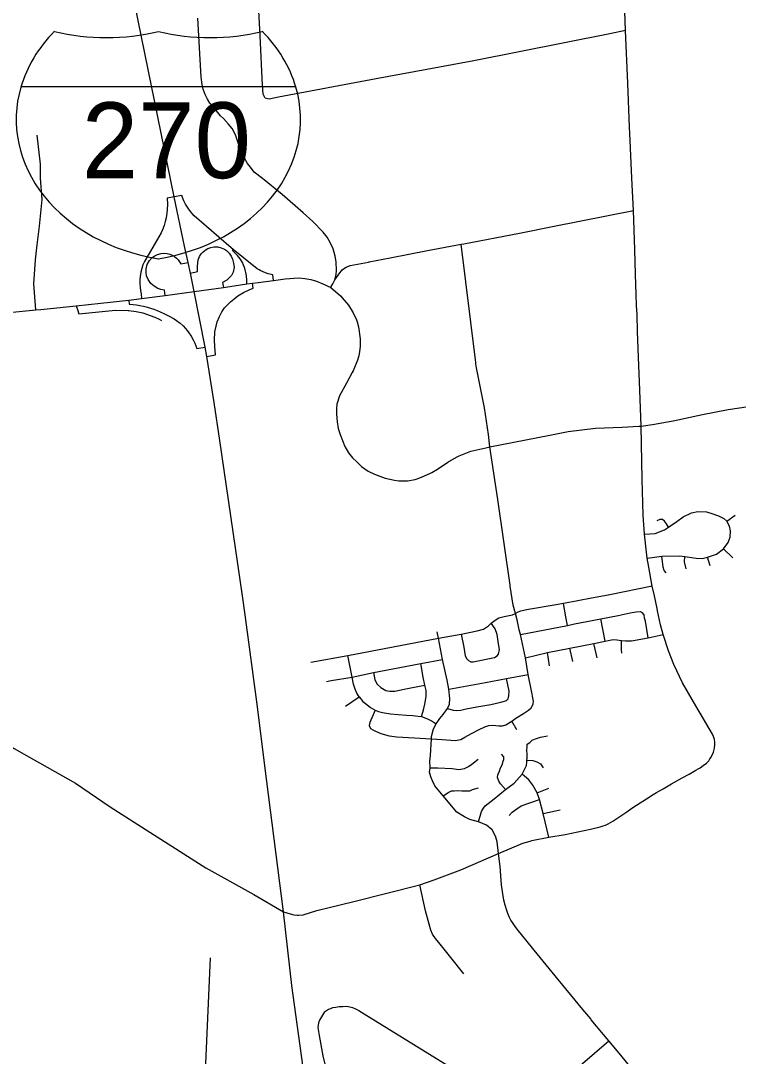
# Model space of a CAD drawing. Extents: x 1755200 to 1902939, y 644115 to 788070.
# Drawn here: x 1791519 to 1800983, y 731049 to 744708 of the extents above; entities that cross this region are included whole.
import ezdxf

# ---------------------------------------------------------------- set-up
doc = ezdxf.new("R2010")
doc.units = 0
for name, color, linetype in [('GM_X_City_Street', 7, 'Continuous'), ('GM_X_County_Road', 7, 'Continuous'), ('GM_X_Interchange_Ramps', 7, 'Continuous'), ('GM_X_Interstate_Route', 7, 'Continuous'), ('GM_X_Interstate_Shield', 7, 'Continuous'), ('GM_X_Township_Road', 7, 'Continuous')]:
    doc.layers.add(name, color=color, linetype=linetype)

msp = doc.modelspace()

# ---------------------------------------------------------------- linework, layer by layer
at = {"layer": 'GM_X_City_Street'}
for points in [[(1799549, 743305), (1799525, 743884), (1799496, 744577), (1799472, 745204), (1799470, 745250)], [(1795663, 741290), (1795678, 741361), (1795683, 741414), (1795679, 741527), (1795668, 741602), (1795639, 741699), (1795602, 741783), (1795561, 741853), (1795507, 741919), (1795370, 742058), (1795243, 742175), (1794967, 742417), (1794706, 742627), (1794600, 742710), (1794548, 742777), (1794511, 742823), (1794469, 742896), (1794397, 743073), (1794350, 743203), (1794310, 743288), (1794261, 743343), (1794192, 743419), (1794155, 743455), (1794083, 743543), (1794013, 743621), (1793984, 743671), (1793952, 743733), (1793927, 743805), (1793912, 743865), (1793901, 743964), (1793856, 744742)], [(1799496, 744577), (1799289, 744537)], [(1791719, 740894), (1791693, 741238), (1791715, 741554), (1791737, 741750), (1791769, 742000), (1791802, 742349), (1791780, 742632), (1791780, 742818), (1791737, 743199)], [(1792575, 740984), (1792943, 741023), (1793111, 741042), (1793423, 741084), (1793807, 741137), (1794194, 741191), (1794500, 741239), (1794577, 741246), (1794650, 741255), (1794852, 741283), (1795006, 741303), (1795067, 741309), (1795123, 741314), (1795192, 741315), (1795267, 741308), (1795345, 741293), (1795422, 741272), (1795505, 741238), (1795608, 741189), (1795616, 741203)], [(1795616, 741203), (1795636, 741236), (1795663, 741290), (1795705, 741352), (1795726, 741382), (1795748, 741410), (1795761, 741423)], [(1795608, 741189), (1795735, 741080), (1795787, 741024), (1795844, 740955), (1795905, 740857), (1795947, 740763), (1795955, 740734)], [(1799686, 739836), (1799686, 739837), (1799668, 740268), (1799655, 740610), (1799648, 740830), (1799643, 740956), (1799637, 741097)], [(1785644, 740199), (1786132, 740262), (1786526, 740311), (1786898, 740356), (1787185, 740392), (1787465, 740426), (1788258, 740523), (1789260, 740650), (1790792, 740800), (1791719, 740894), (1791786, 740901)], [(1791786, 740901), (1792249, 740949), (1792575, 740984)], [(1792249, 740949), (1792266, 740900), (1792287, 740842), (1792680, 740880), (1792769, 740889), (1792938, 740884)], [(1792938, 740884), (1792945, 740884), (1793040, 740874), (1793130, 740856), (1793290, 740797), (1793344, 740773), (1793376, 740755)], [(1795955, 740734), (1795974, 740669), (1795997, 740511), (1795995, 740409), (1795989, 740343), (1795979, 740286), (1795963, 740232), (1795903, 740091), (1795892, 740070)], [(1797523, 740183), (1797520, 740200), (1797516, 740235)], [(1795892, 740070), (1795814, 739927), (1795724, 739761), (1795689, 739652), (1795682, 739594), (1795682, 739520), (1795691, 739416), (1795707, 739330), (1795733, 739250), (1795796, 739091), (1795843, 739007), (1795893, 738943), (1795951, 738888), (1796013, 738827), (1796101, 738765), (1796186, 738727), (1796328, 738676), (1796450, 738646), (1796505, 738641), (1796619, 738639), (1796722, 738657), (1796784, 738678), (1796916, 738736), (1796940, 738750)], [(1796940, 738750), (1797017, 738793), (1797153, 738883), (1797265, 738949), (1797300, 738970), (1797458, 739032), (1797655, 739076), (1797706, 739086)], [(1799747, 737936), (1799887, 737946), (1800011, 737994), (1800061, 738029), (1800172, 738101), (1800255, 738162), (1800366, 738216), (1800452, 738233), (1800563, 738231), (1800636, 738210), (1800722, 738178), (1800792, 738141), (1800833, 738105)], [(1800833, 738105), (1800943, 738188)], [(1799783, 737618), (1799973, 737646), (1800212, 737649), (1800280, 737640), (1800426, 737618), (1800508, 737615), (1800577, 737632), (1800694, 737673), (1800787, 737744), (1800849, 737826), (1800875, 737895), (1800881, 737978), (1800866, 738039), (1800833, 738105)], [(1800061, 738029), (1800035, 738072), (1800009, 738108), (1799982, 738127), (1799949, 738128), (1799910, 738112)], [(1800787, 737744), (1800911, 737622)], [(1800031, 737424), (1800004, 737458), (1799991, 737499), (1799973, 737646)], [(1800295, 737478), (1800274, 737569), (1800280, 737640)], [(1800612, 737516), (1800577, 737632)], [(1798045, 736887), (1798016, 736998), (1797975, 737251)], [(1799073, 737095), (1799048, 737091), (1798867, 737055)], [(1798557, 736998), (1798218, 736940), (1798110, 736918), (1798075, 736905), (1798045, 736887)], [(1798733, 736729), (1798709, 736844), (1798679, 737019)], [(1800494, 735551), (1800455, 735618), (1800249, 735973), (1800132, 736217), (1800061, 736396), (1799991, 736610), (1799957, 736739), (1799918, 736926), (1799912, 736953)], [(1797031, 736564), (1797328, 736616), (1797540, 736660), (1797624, 736681), (1797687, 736727), (1797724, 736760), (1797778, 736801), (1797827, 736830), (1797895, 736851), (1797962, 736862), (1798006, 736873), (1798045, 736887)], [(1798252, 735645), (1798270, 735675), (1798279, 735699), (1798282, 735732), (1798277, 735755), (1798254, 735869), (1798211, 736086), (1798177, 736306), (1798112, 736612), (1798095, 736673), (1798069, 736806), (1798045, 736887)], [(1798112, 736612), (1798733, 736729), (1798823, 736751), (1799170, 736818), (1799398, 736861), (1799557, 736899), (1799638, 736911), (1799690, 736917), (1799717, 736902)], [(1799227, 736523), (1799170, 736818)], [(1799795, 736566), (1799758, 736787), (1799748, 736827), (1799740, 736870), (1799717, 736902)], [(1797328, 736616), (1797362, 736447), (1797383, 736332), (1797403, 736292), (1797425, 736269), (1797454, 736253), (1797487, 736252), (1797770, 736310), (1797803, 736329), (1797823, 736353), (1797836, 736414), (1797823, 736489), (1797803, 736611), (1797777, 736689), (1797724, 736760)], [(1795345, 736249), (1795832, 736336), (1797031, 736564)], [(1797820, 733723), (1797802, 733878), (1797787, 733940), (1797761, 733998), (1797737, 734036), (1797662, 734099), (1797556, 734140), (1797441, 734173), (1797373, 734207), (1797273, 734267), (1797093, 734482), (1796983, 734618), (1796950, 734682), (1796927, 734733), (1796909, 734795), (1796920, 734854), (1796916, 734942), (1796925, 735014), (1796936, 735234), (1796937, 735265), (1796962, 735366), (1796997, 735432), (1797048, 735506), (1797092, 735556), (1797150, 735638), (1797175, 735693), (1797181, 735767), (1797167, 735892), (1797142, 736010), (1797081, 736283), (1797031, 736564), (1797012, 736647)], [(1798177, 736306), (1798467, 736374), (1798762, 736430), (1799076, 736493), (1799227, 736523), (1799266, 736531), (1799333, 736545), (1799383, 736543), (1799445, 736533), (1799495, 736527), (1799576, 736529), (1799795, 736566), (1799991, 736610)], [(1799448, 736367), (1799445, 736414), (1799445, 736533)], [(1798801, 736256), (1798762, 736430)], [(1799121, 736304), (1799076, 736493)], [(1795614, 736004), (1795891, 736051), (1796170, 736110), (1796795, 736230), (1797081, 736283)], [(1795982, 735790), (1795952, 735840), (1795931, 735892), (1795908, 735957), (1795891, 736051), (1795873, 736137), (1795832, 736336)], [(1798495, 736200), (1798467, 736374)], [(1796170, 736110), (1796190, 736016), (1796221, 735958), (1796269, 735911), (1796337, 735874), (1796386, 735863), (1796454, 735866), (1796578, 735889), (1796688, 735914), (1796850, 735945)], [(1796805, 735529), (1796825, 735586), (1796837, 735635), (1796851, 735693), (1796857, 735743), (1796868, 735800), (1796865, 735873), (1796850, 735945), (1796828, 736051), (1796795, 736230)], [(1795553, 735993), (1795614, 736004)], [(1797150, 735638), (1797224, 735613), (1797267, 735610), (1797326, 735616), (1797394, 735631), (1797537, 735656), (1797719, 735690), (1797852, 735718), (1797898, 735733), (1797926, 735743), (1797948, 735764), (1797957, 735804), (1797960, 735863), (1797926, 736030)], [(1797167, 735892), (1797648, 735978), (1797926, 736030), (1798211, 736086)], [(1790451, 735756), (1790572, 735640), (1791432, 735108), (1791596, 735016)], [(1795802, 735665), (1795982, 735790)], [(1795982, 735790), (1796033, 735729), (1796084, 735688), (1796132, 735648), (1796195, 735615), (1796239, 735597), (1796291, 735582), (1796398, 735566), (1796497, 735556), (1796607, 735548), (1796691, 735544), (1796762, 735536), (1796805, 735529), (1796884, 735500), (1796944, 735467), (1796997, 735432)], [(1796195, 735615), (1796122, 735450), (1796117, 735412), (1796132, 735374), (1796162, 735353), (1796198, 735336), (1796271, 735308), (1796380, 735275), (1796482, 735262), (1796715, 735247), (1796936, 735234), (1797079, 735226), (1797249, 735216), (1797323, 735229), (1797376, 735256), (1797465, 735305), (1797558, 735355), (1797640, 735396), (1797695, 735411), (1797747, 735414), (1797825, 735407), (1797873, 735407), (1797917, 735422), (1797995, 735467), (1798050, 735508), (1798150, 735571), (1798216, 735615), (1798252, 735645)], [(1798064, 735353), (1797995, 735467)], [(1797556, 734140), (1797598, 734279), (1797622, 734323), (1797646, 734352), (1797764, 734443), (1797911, 734567), (1798027, 734653), (1798132, 734771), (1798163, 734833), (1798188, 734885), (1798196, 734929), (1798196, 734955), (1798197, 734975), (1798198, 735031), (1798196, 735091), (1798201, 735125), (1798201, 735166)], [(1798201, 735166), (1798234, 735188), (1798264, 735218), (1798310, 735234), (1798376, 735257), (1798468, 735276)], [(1791596, 735016), (1792240, 734652), (1792700, 734340), (1793224, 734005), (1793962, 733534), (1794593, 733184), (1794983, 732956), (1795071, 732926), (1795122, 732913), (1795164, 732910)], [(1797911, 734567), (1797849, 734644), (1797824, 734678), (1797806, 734727), (1797811, 734759), (1797832, 734811), (1797848, 734853), (1797867, 734893), (1797884, 734941), (1797890, 734963), (1797890, 734999), (1797861, 735034)], [(1796920, 734854), (1797020, 734853), (1797210, 734846), (1797298, 734833), (1797372, 734846), (1797423, 734873), (1797471, 734901), (1797551, 734969)], [(1798196, 734955), (1798272, 734949), (1798328, 734934), (1798374, 734904), (1798409, 734852)], [(1798483, 733938), (1798411, 734250), (1798362, 734434), (1798329, 734525), (1798273, 734625), (1798222, 734694), (1798164, 734743), (1798132, 734771)], [(1797093, 734482), (1797164, 734531), (1797201, 734549), (1797237, 734552), (1797275, 734556), (1797337, 734549), (1797393, 734550), (1797441, 734551), (1797478, 734567), (1797558, 734588)], [(1798262, 733893), (1798483, 733938), (1798701, 733975), (1799035, 734046), (1799160, 734074), (1799202, 734087), (1799231, 734097), (1799268, 734116), (1799328, 734150), (1799447, 734228), (1799512, 734275), (1799581, 734322), (1799639, 734362), (1799771, 734446), (1799859, 734501), (1799906, 734528)], [(1798329, 734525), (1798486, 734584)], [(1797960, 734224), (1798003, 734267), (1798061, 734313), (1798119, 734350), (1798362, 734434)], [(1798411, 734250), (1798634, 734300)], [(1797820, 733723), (1798141, 733860), (1798237, 733888), (1798262, 733893)], [(1795164, 732910), (1795182, 732909), (1795244, 732914), (1795424, 732970), (1795913, 733091), (1796785, 733312), (1796971, 733375), (1797324, 733510), (1797820, 733723)], [(1798935, 731665), (1798609, 732063), (1798293, 732448), (1798180, 732586), (1798086, 732702), (1798040, 732762), (1798005, 732814), (1797985, 732846), (1797966, 732881), (1797944, 732930), (1797929, 732971), (1797907, 733040), (1797889, 733110), (1797876, 733193), (1797862, 733309), (1797843, 733550), (1797820, 733723)], [(1797365, 732136), (1797191, 732352), (1797053, 732529), (1796991, 732603), (1796951, 732660), (1796927, 732713), (1796908, 732790), (1796860, 732969), (1796785, 733312)], [(1793942, 730433), (1793952, 730754), (1794024, 732346)], [(1795525, 731633), (1795458, 731526), (1795447, 731490), (1795440, 731428), (1795456, 731323), (1795505, 731053), (1795552, 730857), (1795586, 730777), (1795614, 730752), (1795653, 730719), (1795806, 730569), (1796119, 730282), (1796173, 730235), (1796219, 730205), (1796248, 730197), (1796280, 730183), (1796360, 730154), (1796951, 729939), (1796984, 729920), (1796998, 729899), (1797007, 729860), (1797006, 729824), (1797004, 729769)], [(1795525, 731633), (1795577, 731669), (1795611, 731680), (1795637, 731692), (1795677, 731698), (1795721, 731704), (1795768, 731705), (1795816, 731709), (1795858, 731703), (1795894, 731694), (1795936, 731675), (1795980, 731654), (1796051, 731610), (1797360, 730801), (1797899, 730474), (1797968, 730430), (1798004, 730398), (1798043, 730353), (1798117, 730257)], [(1799037, 731541), (1798935, 731665)], [(1799277, 731252), (1799045, 731531), (1799037, 731541)], [(1797642, 729852), (1797690, 729893), (1797988, 730145), (1798117, 730257), (1798380, 730474), (1798609, 730681), (1798930, 730954), (1799277, 731252)], [(1799803, 730599), (1799551, 730919), (1799391, 731116), (1799277, 731252)]]:
    msp.add_lwpolyline(points, dxfattribs=at)
at = {"layer": 'GM_X_County_Road'}
for points in [[(1799637, 741097), (1799627, 741366), (1799618, 741691), (1799603, 742203), (1799579, 742632), (1799552, 743225), (1799549, 743305)], [(1797364, 741767), (1798098, 741907), (1798557, 741999), (1799603, 742203)], [(1796113, 741527), (1796394, 741580), (1796886, 741676), (1797329, 741761), (1797364, 741767)], [(1797516, 740235), (1797329, 741761)], [(1795761, 741423), (1795775, 741437), (1795813, 741458), (1795866, 741479), (1796106, 741525), (1796113, 741527)], [(1797975, 737251), (1797973, 737264), (1797810, 738392), (1797706, 739086), (1797689, 739251), (1797637, 739603), (1797532, 740130), (1797523, 740183)], [(1799703, 739362), (1799686, 739836)], [(1799670, 739360), (1799703, 739362), (1799850, 739382), (1800126, 739432), (1800512, 739513), (1800852, 739578), (1801237, 739639), (1801420, 739674)], [(1797706, 739086), (1798496, 739242), (1798740, 739291), (1799100, 739335), (1799450, 739346), (1799670, 739360)], [(1799912, 736953), (1799878, 737120), (1799846, 737251), (1799802, 737499), (1799783, 737618), (1799747, 737936), (1799728, 738186), (1799717, 738661), (1799703, 739362)], [(1800456, 734839), (1800482, 734854), (1800522, 734882), (1800563, 734915), (1800593, 734947), (1800610, 734972), (1800624, 734993), (1800655, 735059), (1800669, 735113), (1800674, 735162), (1800674, 735194), (1800671, 735225), (1800658, 735266), (1800642, 735297), (1800600, 735374), (1800494, 735551)], [(1799906, 734528), (1799992, 734576), (1800104, 734642), (1800244, 734721), (1800336, 734772), (1800425, 734821), (1800456, 734839)]]:
    msp.add_lwpolyline(points, dxfattribs=at)
at = {"layer": 'GM_X_Interchange_Ramps'}
for points in [[(1794852, 741283), (1794845, 741357), (1794784, 741371), (1794746, 741383), (1794715, 741395), (1794686, 741408), (1794663, 741420), (1794636, 741436), (1794323, 741691), (1794295, 741714), (1793808, 742135), (1793780, 742165), (1793757, 742193), (1793735, 742223), (1793717, 742249), (1793693, 742290), (1793671, 742333), (1793654, 742374), (1793643, 742404), (1793541, 742384)], [(1793541, 742384), (1793451, 742366), (1793453, 742283), (1793452, 742216), (1793448, 742168), (1793438, 742109), (1793426, 742058), (1793410, 742006), (1793388, 741950), (1793370, 741911), (1793340, 741857), (1793152, 741532), (1793131, 741486), (1793115, 741441), (1793102, 741390), (1793093, 741336), (1793089, 741293), (1793089, 741240), (1793093, 741191), (1793100, 741151), (1793108, 741104), (1793111, 741042)], [(1793758, 741379), (1793852, 741398), (1793850, 741470), (1793861, 741553), (1793878, 741598), (1793899, 741631), (1793920, 741656), (1793952, 741683), (1793989, 741704), (1794026, 741718), (1794068, 741725), (1794120, 741724), (1794165, 741714), (1794205, 741695), (1794234, 741676), (1794270, 741642), (1794297, 741602), (1794313, 741564), (1794325, 741511), (1794334, 741451), (1794322, 741393), (1794300, 741349), (1794274, 741321), (1794237, 741287), (1794181, 741254), (1794194, 741191)], [(1793423, 741084), (1793415, 741154), (1793369, 741163), (1793326, 741176), (1793281, 741207), (1793236, 741244), (1793198, 741295), (1793179, 741344), (1793172, 741388), (1793173, 741434), (1793188, 741491), (1793217, 741544), (1793252, 741583), (1793286, 741607), (1793323, 741625), (1793370, 741638), (1793415, 741642), (1793451, 741638), (1793486, 741629), (1793516, 741616), (1793549, 741596), (1793574, 741575), (1793595, 741552), (1793631, 741501), (1793727, 741520)], [(1794500, 741239), (1794501, 741285), (1794495, 741343), (1794487, 741387), (1794478, 741422), (1794469, 741452), (1794457, 741485), (1794443, 741517), (1794430, 741540), (1794413, 741569), (1794377, 741610), (1794313, 741679), (1794323, 741691)], [(1793974, 740278), (1794087, 740299), (1794079, 740412), (1794073, 740493), (1794081, 740605), (1794095, 740677), (1794112, 740734), (1794141, 740805), (1794173, 740866), (1794207, 740919), (1794288, 741000), (1794328, 741036), (1794385, 741078), (1794457, 741124), (1794532, 741160), (1794583, 741179), (1794577, 741246)], [(1792943, 741023), (1792949, 740970), (1793003, 740965), (1793048, 740959), (1793091, 740952), (1793140, 740941), (1793193, 740928), (1793230, 740917), (1793277, 740902), (1793321, 740885), (1793360, 740869), (1793399, 740851), (1793487, 740807), (1793541, 740776), (1793575, 740753), (1793622, 740717), (1793660, 740682), (1793691, 740649), (1793715, 740621), (1793738, 740591), (1793767, 740547), (1793794, 740499), (1793814, 740456), (1793842, 740383), (1793952, 740404)]]:
    msp.add_lwpolyline(points, dxfattribs=at)
at = {"layer": 'GM_X_Interstate_Route'}
for points in [[(1793680, 741736), (1793541, 742384), (1792510, 747451), (1792028, 749783)], [(1794145, 739169), (1794072, 739672), (1793974, 740278), (1793952, 740404), (1793807, 741137), (1793758, 741379), (1793727, 741520), (1793680, 741736)], [(1794438, 737151), (1794145, 739169)], [(1794740, 734878), (1794642, 735660), (1794478, 736870), (1794438, 737151)], [(1795311, 729935), (1795293, 730422), (1795244, 730841), (1795239, 730931), (1795097, 731981), (1794983, 732956), (1794740, 734878)]]:
    msp.add_lwpolyline(points, dxfattribs=at)
at = {"layer": 'GM_X_Interstate_Shield'}
msp.add_line((1795148, 743834), (1791522, 743834), dxfattribs=at)
msp.add_line((1795148, 743834), (1791522, 743834), dxfattribs=at)
for centre, start_param, end_param in [((1793803, 743405), 2.47259, 2.911027), ((1792650, 746361), 4.415841, 5.008937), ((1794020, 746361), 4.415841, 5.008937), ((1792866, 743405), 0.230566, 0.669003), ((1793803, 743405), 2.911027, 4.511031), ((1792866, 743405), 4.913747, 6.513751)]:
    msp.add_ellipse(centre, major_axis=(2344, 0), ratio=0.8, start_param=start_param, end_param=end_param, dxfattribs=at)
at = {"layer": 'GM_X_Township_Road'}
for points in [[(1799289, 744537), (1799289, 744537), (1797495, 744179), (1797042, 744094), (1796208, 743940), (1794921, 743699), (1794796, 743673), (1794744, 743685), (1794716, 743741), (1794710, 743860), (1794677, 744507), (1794661, 744839)], [(1799846, 737251), (1799288, 737135), (1799073, 737095)], [(1798867, 737055), (1798679, 737019), (1798557, 736998)]]:
    msp.add_lwpolyline(points, dxfattribs=at)

# ---------------------------------------------------------------- texts
at = {"layer": 'GM_X_Interstate_Shield'}
msp.add_text('270', height=1000, dxfattribs=at).set_placement((1792325, 742631))

doc.saveas('drawing.dxf')
